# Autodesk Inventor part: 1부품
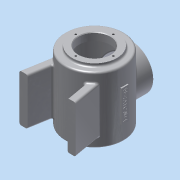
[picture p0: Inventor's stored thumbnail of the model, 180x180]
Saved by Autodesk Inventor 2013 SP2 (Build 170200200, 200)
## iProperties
Created: 2015-01
Part Number: 1부품
Material: 알루미늄 6061
Document SubType Name: Modeling
Designer: dgall
Density: 2.71 g/cm^3
Mass: 1021.13 g
Surface Area: 1060.37 cm^2
Volume: 376.8 cm^3
Author: dgall
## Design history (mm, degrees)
sketch "스케치1"
  geometry: C1 r 50 at (0, 0); 1 further point
  constraints: 1 centre point, 1 coincident
  dimensions: "d4" = 100 diameter of C1
extrude "돌출1" new body sketch "스케치1" distance "d1" = 112; taper "d2" = 0 deg
node "작업 평면1"
sketch "스케치2"
  geometry: C1 r 38 at (0, 0); 1 further point
  constraints: 1 centre point, 1 coincident
  dimensions: "d7" = 38 radius of C1
extrude "돌출2" join sketch "스케치2" distance "d9" = 122; taper "d10" = 0 deg
sketch "스케치3"
  geometry: C1 r 38 at (0, 0) reference; C2 r 27 at (0, 0)
  constraints: 1 centre point, 1 coincident
  dimensions: "d11" = 27 radius of C2
extrude "돌출3" cut sketch "스케치3" distance "d12" = 122; taper "d13" = 0 deg
node "작업 평면2"
sketch "스케치4"
  geometry: C1 r 45 at (0, 0); 1 further point
  constraints: 1 centre point, 1 coincident
  dimensions: "d15" = 45 radius of C1
extrude "돌출4" cut sketch "스케치4" distance "d16" = 97; taper "d17" = 0 deg
node "작업 평면3"
sketch "스케치5"
  geometry: L1 (-38, 117)-(38, 117) reference; L2 (-50, 0)-(-50, 112) reference; C1 r 38 at (0, 55); 3 further points
  constraints: 2 midpoint, 1 centre point, 1 vertical alignment
  dimensions: "d81" = 38 radius of C1; "d82" = 62 distance from line of L1 C1.centre
extrude "돌출5" join sketch "스케치5" stored distance "d20" = 97; taper "d21" = 0 deg
sketch "스케치8"
  geometry: C1 r 27 at (0, 0) reference; 1 further point
  constraints: 1 vertical alignment
  dimensions: "d37" = 32 distance of C1.centre point (0, 32)
hole "구멍2" sketch "스케치8" at (0, 32) diameter "d38" = 3.242; stored, may be unused: countersink angle "d42" = 90 deg, drill point angle "d44" = 118 deg; dims "d39" = 8, "d40" = 4, "d41" = 2, "d43" = 10
node "작업 평면4"
node "작업 평면5"
sketch "스케치9"
  geometry: L1 (-38, 117)-(38, 117) reference; L2 (6, 82)-(-6, 82); L3 (-6, 82)-(-6, 28); L4 (-6, 28)-(6, 28); L5 (6, 28)-(6, 82); 5 further points
  constraints: 8 end point, 3 midpoint, 2 coincident, 2 parallel, 1 horizontal, 1 perpendicular, 1 vertical alignment
  dimensions: "d48" = 54 distance of L4.end L2.start; "d50" = 12 distance of L2.start L2.end; "d83" = 62 distance from line of L1 point (6, 55)
extrude "돌출7" join sketch "스케치9" distance "d51" = 2; taper "d52" = 0 deg
sketch "스케치11"
  geometry: L1 (-82, 6)-(-82, -6) reference; L2 (-28, 6)-(-82, 6) reference; 4 further points
  constraints: 2 midpoint, 1 horizontal alignment, 1 vertical alignment, 1 other
feature "엠보싱1" sketch "스케치11" dims "d4" = 100, "d53" = 0.5, "d54" = 0
node "작업 평면6"
sketch "스케치12"
  geometry: L1 (6, 82)-(-6, 82) reference; L2 (-6, 82)-(-6, 28) reference; L3 (6, 28)-(6, 82) reference; L4 (-6, 28)-(6, 28) reference; 1 further point
extrude "돌출8" join sketch "스케치12" stored distance "d55" = 2; taper "d56" = 0 deg
node "작업 평면7"
sketch "스케치13"
  geometry: L1 (27.282, -41.901)-(34, -80); L2 (34, -80)-(48, -80); L3 (48, -80)-(39.336, -30.865); L4 (-27.282, -41.901)-(-34, -80); L5 (-34, -80)-(-48, -80); L6 (-48, -80)-(-39.336, -30.865); C1 r 45 at (0, 0) reference; A1 r 50 centre (0, 0) between (27.282, -41.901) and (39.336, -30.865) reference; 1 further point
  constraints: 12 end point, 4 point on circle, 1 collinear, 1 horizontal, 1 parallel
  dimensions: "d58" = 14 distance of L1.end L2.end; "d60" = 80 deg angle of L2 L1; "d62" = 14 distance of L4.end L5.end; "d63" = 80 deg angle of L5 L4; "d64" = 100 deg angle of L5 L6; "d65" = 80 distance from line of point (0, 0) L5; "d66" = 80 distance from line of point (0, 0) L2; "d67" = 96 distance of L2.end L5.end; "d68" = 48 horizontal distance of point (0, 0) L5.end
extrude "돌출9" join sketch "스케치13" distance "d69" = 80; taper "d70" = 0 deg
fillet "모깎기1" dims "d71" = 3
fillet "모깎기2" dims "d72" = 3
chamfer "모따기1" distance "d73" = 1; stored, may be unused: second distance "d74" = 2, angle "d75" = 45 deg
fillet "모깎기3" dims "d76" = 3
fillet "모깎기4" dims "d77" = 3
fillet "모깎기5" dims "d78" = 3
fillet "모깎기6" dims "d79" = 3
sketch "스케치14"
  geometry: C1 r 38 at (0, 0) reference; C2 r 27 at (0, 0); 1 further point
  constraints: 1 centre point, 1 coincident
  dimensions: "d84" = 27 radius of C2
extrude "돌출10" cut sketch "스케치14" stored distance "d85" = 80; taper "d86" = 0 deg
sketch "스케치15"
  geometry: C1 r 27 at (0, 0) reference; 2 further points
  constraints: 1 vertical alignment
  dimensions: "d88" = 32 distance of C1.centre point (0, 32)
hole "구멍3" sketch "스케치15" at (0, 32) diameter "d89" = 3.242; stored, may be unused: countersink angle "d93" = 90 deg, drill point angle "d95" = 118 deg; dims "d90" = 8, "d91" = 4, "d92" = 2, "d94" = 10
fillet "모깎기8" dims "d99" = 3
fillet "모깎기9" dims "d100" = 3
chamfer "모따기2" distance "d101" = 1; stored, may be unused: second distance "d102" = 2, angle "d103" = 45 deg
sketch "스케치18"
  geometry: C1 r 27 at (0, 0) reference; C2 r 45 at (0, 0) reference
extrude "돌출13" cut sketch "스케치18" distance "d108" = 1; taper "d109" = 0 deg
sketch "스케치19"
  geometry: C1 r 27 at (0, 0) reference; C2 r 45 at (0, 0) reference
extrude "돌출14" join sketch "스케치19" distance "d110" = 1; taper "d111" = 0 deg
fillet "모깎기10" dims "d112" = 3
node "솔리드1"
pattern_circular "원형 패턴2" dims angle "d46" = 360 deg
mirror "대칭1"
pattern_circular "원형 패턴3" dims angle "d97" = 360 deg
node "절단 모서리 투영1"
other parameters: "d6" = 5, "d14" = -7, "d18" = 62, "d57" = -21
